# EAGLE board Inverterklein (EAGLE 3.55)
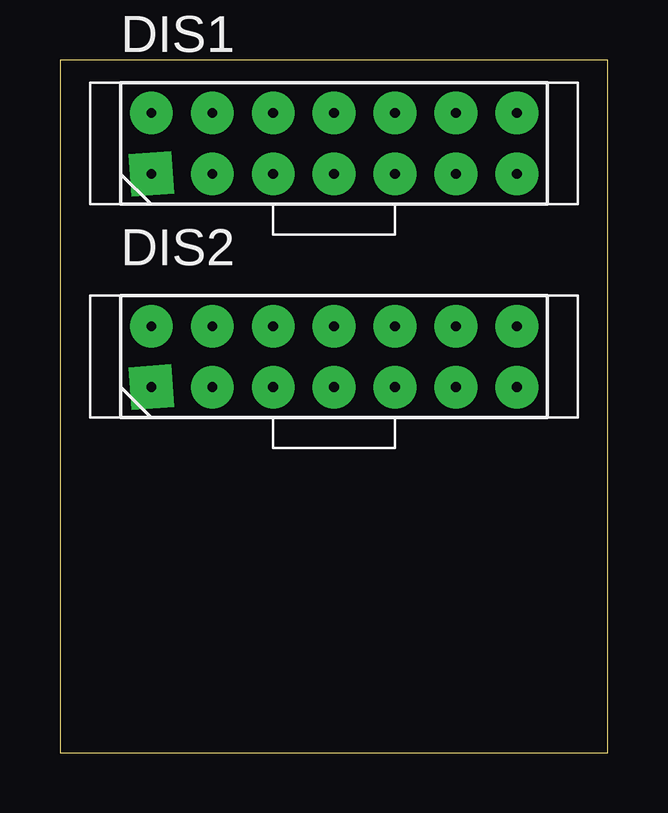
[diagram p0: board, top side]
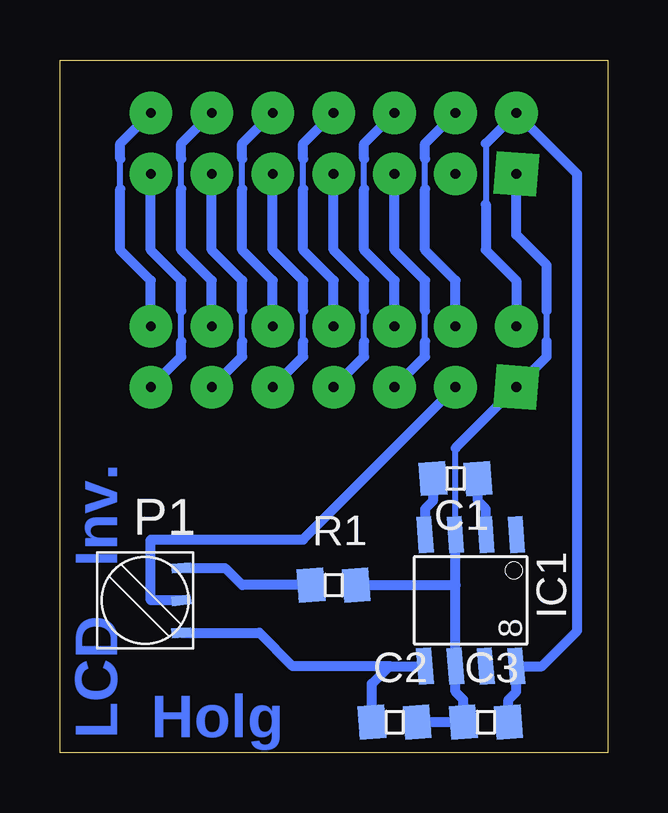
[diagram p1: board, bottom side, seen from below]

Size 22.84 x 28.88 mm. Coordinates in mm from the lower left corner, seen from the top.
Outline: 0,0 22.84,0 22.84,28.88 0,28.88 0,0
Copper layers used: Bottom

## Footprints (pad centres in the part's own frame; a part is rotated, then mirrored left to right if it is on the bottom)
05 = smd 1.092 x 1.397 rotated 4.4:  0.94,0 | smd 1.092 x 1.397 rotated 4.3:  -0.94,0
7 = drill 0.406 pad 1.778 square:  0,0 | drill 0.406 pad 1.778 round:  2.54,0;  5.08,0;  7.62,0;  10.16,0;  10.16,2.54;  7.62,2.54;  5.08,2.54;  2.54,2.54;  0,2.54;  12.7,0;  12.7,2.54;  15.24,0;  15.24,2.54
8 = smd 0.61 x 1.524 rotated 4.3:  -2.54,-2.743 | smd 0.61 x 1.524 rotated 4.9:  -2.54,2.743 | smd 0.61 x 1.524 rotated 4.4:  -1.27,-2.743 | smd 0.61 x 1.524 rotated 4.5:  0,-2.743 | smd 0.61 x 1.524 rotated 4.8:  -1.27,2.743 | smd 0.61 x 1.524 rotated 4.7:  0,2.743;  1.27,2.743 | smd 0.61 x 1.524 rotated 4.6:  1.27,-2.743
IMMER = smd 0.406 x 0.813 rotated 7.3:  0,0 | smd 0.406 x 0.813 rotated 3.8:  1.35,0 | smd 0.406 x 0.813 rotated 4:  -1.35,0

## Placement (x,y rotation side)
C1  100n  [05]  6.35,11.43 0 bottom
C2  100n  [05]  8.89,1.27 0 bottom
C3  100n  [05]  5.08,1.27 0 bottom
DIS1  LCD In  [7]  3.81,24.13 0 top
DIS2  LCD Out  [7]  3.81,15.24 0 top
IC1  ICL7660SMD  [8]  6.35,6.35 180 bottom
P1  10k  [IMMER]  17.78,6.35 90 bottom
R1  22k  [05]  11.43,6.99 0 bottom

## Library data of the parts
C1-C3 P1 R1 = Holgsmd
DIS1 DIS2 = 8031bord
IC1 = ic_holg

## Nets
+5V: C3. DIS1. DIS2. IC1.
GND: C2. C3. DIS1. DIS2. IC1. R1.
N$1: DIS1. DIS2.
N$2: DIS1. DIS2.
N$3: DIS1. DIS2.
N$4: DIS1. DIS2.
N$5: DIS1. DIS2.
N$6: DIS1. DIS2.
N$7: DIS1. DIS2.
N$8: DIS1. DIS2.
N$9: DIS1. DIS2.
N$10: DIS2. P1.
N$11: DIS1. DIS2.
N$12: P1. R1.
N$13: DIS1. DIS2.
N$83: C1. IC1.
N$84: C1. IC1.
VOUT: C2. IC1. P1.

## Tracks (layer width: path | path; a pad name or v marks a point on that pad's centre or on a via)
+5V
  Bottom 0.254: 5.08,25.4 5.08,22.86
  Bottom 0.406: 5.08,25.4 3.81,26.67 1.27,24.13 1.27,5.08 2.74,3.61 3.81,3.61 3.81,2.54 4.14,2.21 4.14,1.27 | 3.81,17.78 3.81,19.68 5.08,20.95 5.08,22.86
GND
  Bottom 0.254: 2.54,17.14 2.54,18.41 | 6.35,9.09 6.35,12.7
  Bottom 0.406: 3.81,24.13 3.81,21.59 2.54,20.32 2.54,18.41 | 2.54,17.14 2.54,16.51 3.81,15.24 6.35,12.7 | 7.95,1.27 C3. 6.02,2.21 6.35,2.54 6.35,3.61 6.35,6.99 | 6.35,6.99 6.35,9.09 | 10.49,6.99 6.35,6.99
N$1
  Bottom 0.254: 10.16,17.14 10.16,18.41
  Bottom 0.406: 11.43,24.13 11.43,20.95 10.16,19.68 10.16,18.41 | 11.43,15.24 10.16,16.51 10.16,17.14
N$2
  Bottom 0.254: 10.16,23.5 10.16,24.77
  Bottom 0.406: 8.89,26.67 10.16,25.4 10.16,24.77 | 8.89,17.78 8.89,19.68 10.16,20.95 10.16,23.5
N$3
  Bottom 0.254: 12.7,23.5 12.7,24.77
  Bottom 0.406: 11.43,26.67 12.7,25.4 12.7,24.77 | 11.43,17.78 11.43,19.68 12.7,20.95 12.7,23.5
N$4
  Bottom 0.254: 12.7,17.14 12.7,18.41
  Bottom 0.406: 13.97,24.13 13.97,20.95 12.7,19.68 12.7,18.41 | 13.97,15.24 12.7,16.51 12.7,17.14
N$5
  Bottom 0.254: 15.24,23.5 15.24,24.77
  Bottom 0.406: 13.97,26.67 15.24,25.4 15.24,24.77 | 13.97,17.78 13.97,19.68 15.24,20.95 15.24,23.5
N$6
  Bottom 0.254: 15.24,17.14 15.24,18.41
  Bottom 0.406: 16.51,24.13 16.51,20.95 15.24,19.68 15.24,18.41 | 16.51,15.24 15.24,16.51 15.24,17.14
N$7
  Bottom 0.254: 7.62,17.14 7.62,18.41
  Bottom 0.406: 8.89,24.13 8.89,20.95 7.62,19.68 7.62,18.41 | 8.89,15.24 7.62,16.51 7.62,17.14
N$8
  Bottom 0.254: 7.62,23.5 7.62,24.77
  Bottom 0.406: 6.35,26.67 7.62,25.4 7.62,24.77 | 6.35,17.78 6.35,19.68 7.62,20.95 7.62,23.5
N$9
  Bottom 0.254: 17.78,23.5 17.78,24.77
  Bottom 0.406: 16.51,26.67 17.78,25.4 17.78,24.77 | 16.51,17.78 16.51,19.68 17.78,20.95 17.78,23.5
N$10
  Bottom 0.406: 17.78,6.35 19.05,6.35 19.05,8.89 12.7,8.89 6.35,15.24
N$11
  Bottom 0.254: 17.78,17.14 17.78,18.41
  Bottom 0.406: 19.05,24.13 19.05,20.95 17.78,19.68 17.78,18.41 | 19.05,15.24 17.78,16.51 17.78,17.14
N$12
  Bottom 0.406: 17.78,7.7 15.96,7.7 15.24,6.99 R1.
N$13
  Bottom 0.254: 20.32,23.5 20.32,24.77
  Bottom 0.406: DIS1. 20.32,25.4 20.32,24.77 | DIS2. 19.05,19.68 20.32,20.95 20.32,23.5
N$83
  Bottom 0.406: 5.08,9.09 5.08,10.16 5.41,10.49 5.41,11.43
N$84
  Bottom 0.406: 7.62,9.09 7.62,10.16 7.29,10.49 C1.
VOUT
  Bottom 0.406: 9.09,3.61 IC1. | C2. 9.83,2.87 9.09,3.61 | P1. 14.53,5 13.13,3.61 9.09,3.61

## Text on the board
Bottom: Inv. | LCD | Holg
